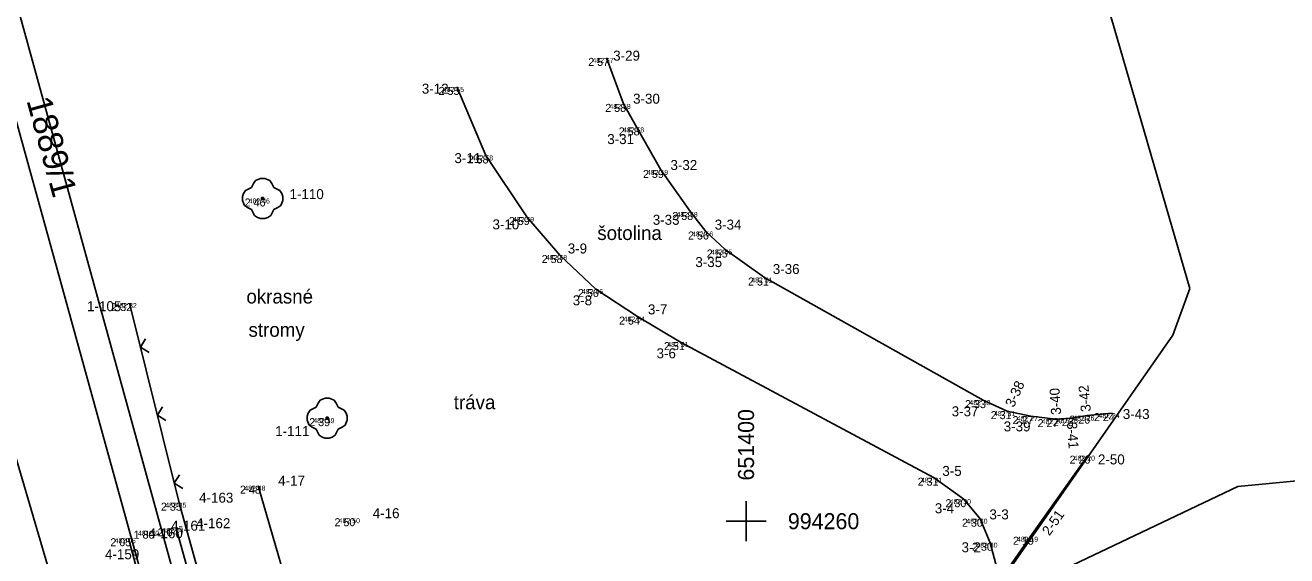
# Model space of a CAD drawing. Extents: x -651478 to -651308, y -994378 to -994071.
# Drawn here: x -651414.41 to -651389.19, y -994260.69 to -994250.09 of the extents above; entities that cross this region are included whole.
import ezdxf

# ---------------------------------------------------------------- set-up
doc = ezdxf.new("R2010")
doc.units = 0
for name, color, linetype in [('13_POPIS_POLOHOPISU', 7, 'Continuous'), ('18_TECKY_BODU', 7, 'Continuous'), ('19_CISLA_BODU', 7, 'Continuous'), ('20_REDUKOVANE_VYSKY_BODU', 7, 'Continuous'), ('21_SOUVISLA_ZELEN', 7, 'Continuous'), ('22_JEDNOTL_STROMY', 7, 'Continuous'), ('23_BREHOVA_CARA', 7, 'Continuous'), ('25_CHODNIKY', 7, 'Continuous'), ('26_PLOTY', 7, 'Continuous'), ('38_VODA-VEDENI', 7, 'Continuous'), ('61_UPLNE_VYSKY_BODU', 7, 'Continuous'), ('_KM', 7, 'Continuous'), ('ROZP', 7, 'Continuous')]:
    doc.layers.add(name, color=color, linetype=linetype)

# ---------------------------------------------------------------- blocks, each defined once
blk = doc.blocks.new('POINT_DISPLAY')
blk.add_line((0, 0), (0, 0))
blk = doc.blocks.new('Z24')
for p, q in [((-0.22, 0.22), (-0.18, 0.3)), ((-0.18, 0.3), (-0.14, 0.36)), ((-0.14, 0.36), (-0.04, 0.4)), ((-0.04, 0.4), (0.04, 0.4)), ((0.04, 0.4), (0.14, 0.36)), ((0.14, 0.36), (0.18, 0.3)), ((0.18, 0.3), (0.22, 0.22)), ((-0.4, 0.04), (-0.38, 0.1)), ((-0.4, -0.04), (-0.4, 0.04)), ((-0.38, 0.1), (-0.34, 0.16)), ((-0.34, 0.16), (-0.22, 0.22)), ((-0.02, -0.02), (-0.02, 0.02)), ((-0.02, 0.02), (0.02, 0.02)), ((0.02, 0.02), (0.02, -0.02)), ((0.22, 0.22), (0.34, 0.16)), ((0.34, 0.16), (0.38, 0.1)), ((0.38, 0.1), (0.4, 0.04)), ((0.4, 0.04), (0.4, -0.04)), ((-0.36, -0.14), (-0.4, -0.04)), ((-0.3, -0.18), (-0.36, -0.14)), ((-0.22, -0.22), (-0.3, -0.18)), ((-0.16, -0.34), (-0.22, -0.22)), ((0.02, -0.02), (-0.02, -0.02)), ((0.22, -0.22), (0.16, -0.34)), ((0.3, -0.18), (0.22, -0.22)), ((0.36, -0.14), (0.3, -0.18)), ((0.4, -0.04), (0.36, -0.14)), ((-0.1, -0.38), (-0.16, -0.34)), ((-0.04, -0.4), (-0.1, -0.38)), ((0.04, -0.4), (-0.04, -0.4)), ((0.1, -0.38), (0.04, -0.4)), ((0.16, -0.34), (0.1, -0.38))]:
    blk.add_line(p, q)
blk = doc.blocks.new('Z212')
for p, q in [((-0.14, 0.14), (0, 0)), ((0, 0), (0.14, 0.14))]:
    blk.add_line(p, q)
blk = doc.blocks.new('Z70')
for p, q in [((0, -0.4), (0, 0.4)), ((-0.4, 0), (0.4, 0))]:
    blk.add_line(p, q)

msp = doc.modelspace()

# ---------------------------------------------------------------- linework, layer by layer
at = {"layer": '21_SOUVISLA_ZELEN'}
msp.add_line((-651409.75, -994259.29), (-651408.32, -994264.21), dxfattribs=at)
at = {"layer": '23_BREHOVA_CARA'}
for p, q in [((-651411.39, -994260.14), (-651409.85, -994265.67)), ((-651410.87, -994265.87), (-651412.34, -994260.34))]:
    msp.add_line(p, q, dxfattribs=at)
at = {"layer": '25_CHODNIKY'}
for p, q in [((-651402.79, -994250.74), (-651402.45, -994251.66)), ((-651405.2, -994252.69), (-651405.78, -994251.32)), ((-651402.45, -994251.66), (-651402.18, -994252.13)), ((-651402.18, -994252.13), (-651401.7, -994252.98)), ((-651404.38, -994253.92), (-651405.2, -994252.69)), ((-651401.7, -994252.98), (-651401.11, -994253.82)), ((-651401.11, -994253.82), (-651400.8, -994254.21)), ((-651403.72, -994254.68), (-651404.38, -994253.92)), ((-651400.8, -994254.21), (-651400.42, -994254.57)), ((-651400.42, -994254.57), (-651399.63, -994255.13)), ((-651403, -994255.36), (-651403.72, -994254.68)), ((-651402.17, -994255.91), (-651403, -994255.36)), ((-651399.63, -994255.13), (-651395.26, -994257.58)), ((-651401.31, -994256.42), (-651402.17, -994255.91)), ((-651396.24, -994259.13), (-651401.31, -994256.42)), ((-651395.26, -994257.58), (-651394.78, -994257.8)), ((-651394.78, -994257.8), (-651394.31, -994257.9)), ((-651393.18, -994257.89), (-651392.68, -994257.84)), ((-651394.31, -994257.9), (-651393.81, -994257.96)), ((-651393.81, -994257.96), (-651393.51, -994257.94)), ((-651393.51, -994257.94), (-651393.18, -994257.89)), ((-651394.32, -994260.31), (-651393.17, -994258.69)), ((-651395.65, -994259.56), (-651396.24, -994259.13)), ((-651395.32, -994259.95), (-651395.65, -994259.56)), ((-651395.12, -994260.43), (-651395.32, -994259.95)), ((-651397.73, -994265.24), (-651394.32, -994260.31)), ((-651394.96, -994261.03), (-651395.12, -994260.43))]:
    msp.add_line(p, q, dxfattribs=at)
at = {"layer": '26_PLOTY'}
for p, q in [((-651411.33, -994259.63), (-651412.32, -994255.64)), ((-651409.69, -994265.51), (-651411.33, -994259.63))]:
    msp.add_line(p, q, dxfattribs=at)
at = {"layer": '38_VODA-VEDENI'}
for p, q in [((-651396.169, -994262.153), (-651390.168, -994259.308)), ((-651390.168, -994259.308), (-651388.919, -994259.187))]:
    msp.add_line(p, q, dxfattribs=at)
at = {"layer": '_KM'}
for p, q in [((-651417.67, -994238.38), (-651407.11, -994276.82)), ((-651418.3, -994238.56), (-651407.69, -994276.96)), ((-651420.36, -994239.17), (-651409.08, -994277.42)), ((-651391.13, -994255.35), (-651394.42, -994244.03)), ((-651391.47, -994256.28), (-651391.13, -994255.35)), ((-651397.73, -994265.24), (-651391.47, -994256.28))]:
    msp.add_line(p, q, dxfattribs=at)

# ---------------------------------------------------------------- block references
at = {"layer": '18_TECKY_BODU'}
for p in [(-651402.79, -994250.74), (-651405.78, -994251.32), (-651402.45, -994251.66), (-651402.18, -994252.13), (-651405.2, -994252.69), (-651401.7, -994252.98), (-651409.66, -994253.55), (-651401.11, -994253.82), (-651404.38, -994253.92), (-651400.8, -994254.21), (-651400.42, -994254.57), (-651403.72, -994254.68), (-651403, -994255.36), (-651399.63, -994255.13), (-651412.32, -994255.64), (-651402.17, -994255.91), (-651401.31, -994256.42), (-651395.26, -994257.58), (-651394.78, -994257.8), (-651392.68, -994257.84), (-651408.37, -994257.94), (-651394.31, -994257.9), (-651393.81, -994257.96), (-651393.51, -994257.94), (-651393.18, -994257.89), (-651393.17, -994258.69), (-651396.24, -994259.13), (-651409.75, -994259.29), (-651411.33, -994259.63), (-651395.65, -994259.56), (-651411.39, -994260.14), (-651407.86, -994259.94), (-651395.32, -994259.95), (-651412.34, -994260.34), (-651411.89, -994260.19), (-651394.32, -994260.31), (-651395.12, -994260.43)]:
    msp.add_blockref('POINT_DISPLAY', p, dxfattribs=at)
at = {"layer": '22_JEDNOTL_STROMY'}
for p in [(-651409.66, -994253.55), (-651408.37, -994257.94)]:
    msp.add_blockref('Z24', p, dxfattribs=at)
at = {"layer": '26_PLOTY', "rotation": -76.10000000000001}
for p in [(-651412.101, -994256.524), (-651411.763, -994257.883), (-651411.426, -994259.242)]:
    msp.add_blockref('Z212', p, dxfattribs=at)
at = {"layer": 'ROZP'}
msp.add_blockref('Z70', (-651400, -994260), dxfattribs=at)

# ---------------------------------------------------------------- texts
at = {"layer": '13_POPIS_POLOHOPISU'}
for s, p in [('šotolina', (-651402.973, -994254.38)), ('okrasné', (-651409.985, -994255.649)), ('stromy', (-651409.943, -994256.314)), ('tráva', (-651405.841, -994257.763))]:
    msp.add_text(s, height=0.28, dxfattribs=at).set_placement(p)
at = {"layer": '19_CISLA_BODU'}
for s, p in [('3-29', (-651402.655, -994250.795)), ('3-12', (-651406.479, -994251.455)), ('3-30', (-651402.257, -994251.656)), ('3-31', (-651402.773, -994252.463)), ('3-11', (-651405.828, -994252.843)), ('3-32', (-651401.51, -994252.981)), ('1-110', (-651409.123, -994253.563)), ('3-10', (-651405.067, -994254.167)), ('3-33', (-651401.864, -994254.076)), ('3-34', (-651400.626, -994254.172)), ('3-9', (-651403.563, -994254.649)), ('3-35', (-651401.013, -994254.921)), ('3-36', (-651399.465, -994255.06)), ('1-105', (-651413.169, -994255.803)), ('3-8', (-651403.463, -994255.685)), ('3-7', (-651401.96, -994255.867)), ('3-6', (-651401.788, -994256.744)), ('3-37', (-651395.89, -994257.903)), ('3-43', (-651392.47, -994257.958)), ('1-111', (-651409.41, -994258.3)), ('3-39', (-651394.85, -994258.205)), ('3-5', (-651396.077, -994259.095)), ('2-50', (-651392.967, -994258.865)), ('4-17', (-651409.35, -994259.29)), ('4-163', (-651410.93, -994259.63)), ('3-4', (-651396.227, -994259.841)), ('4-16', (-651407.46, -994259.94)), ('3-3', (-651395.136, -994259.964)), ('4-160', (-651411.94, -994260.34)), ('4-161', (-651411.49, -994260.19)), ('4-162', (-651410.99, -994260.14)), ('4-159', (-651412.81, -994260.76)), ('3-2', (-651395.693, -994260.621))]:
    msp.add_text(s, height=0.2, dxfattribs=at).set_placement(p)
for s, rotation, p in [('3-38', 65.3764, (-651394.649, -994257.739)), ('3-40', 93.8142, (-651393.702, -994257.866)), ('3-42', 95.7106, (-651393.106, -994257.804)), ('3-41', 273.8142, (-651393.586, -994258.025)), ('2-51', 54.63, (-651393.937, -994260.303))]:
    msp.add_text(s, height=0.2, rotation=rotation, dxfattribs=at).set_placement(p)
at = {"layer": '20_REDUKOVANE_VYSKY_BODU'}
for s, p in [(' 2 57', (-651403.213, -994250.9)), (' 2 55', (-651406.203, -994251.48)), (' 2 58', (-651402.873, -994251.82)), (' 2 58', (-651402.603, -994252.29)), (' 2 58', (-651405.623, -994252.85)), (' 2 59', (-651402.119, -994253.14)), (' 2 46', (-651410.079, -994253.71)), (' 2 58', (-651401.533, -994253.98)), (' 2 59', (-651404.799, -994254.08)), (' 2 56', (-651401.219, -994254.37)), (' 2 55', (-651400.843, -994254.73)), (' 2 58', (-651404.143, -994254.84)), (' 2 56', (-651403.419, -994255.52)), (' 2 51', (-651400.019, -994255.29)), (' 2 32', (-651412.743, -994255.8)), (' 2 54', (-651402.597, -994256.07)), (' 2 51', (-651401.699, -994256.58)), (' 2 33', (-651395.683, -994257.74)), (' 2 31', (-651395.169, -994257.96)), (' 2 24', (-651393.107, -994258)), (' 2 39', (-651408.789, -994258.1)), (' 2 27', (-651394.733, -994258.06)), (' 2 27', (-651394.233, -994258.12)), (' 2 26', (-651393.929, -994258.1)), (' 2 26', (-651393.599, -994258.05)), (' 2 20', (-651393.593, -994258.85)), (' 2 31', (-651396.629, -994259.29)), (' 2 48', (-651410.173, -994259.45)), (' 2 35', (-651411.753, -994259.79)), (' 2 30', (-651396.073, -994259.72)), (' 2 04', (-651411.817, -994260.3)), (' 2 50', (-651408.283, -994260.1)), (' 2 30', (-651395.743, -994260.11)), (' 2 05', (-651412.763, -994260.5)), (' 1 80', (-651412.298, -994260.35)), (' 2 19', (-651394.724, -994260.47)), (' 2 30', (-651395.543, -994260.59))]:
    msp.add_text(s, height=0.16, dxfattribs=at).set_placement(p)
at = {"layer": '61_UPLNE_VYSKY_BODU'}
for s, p in [('482 57 ', (-651403.068, -994250.84)), ('482 55 ', (-651406.058, -994251.42)), ('482 58 ', (-651402.728, -994251.76)), ('482 58 ', (-651402.458, -994252.23)), ('482 58 ', (-651405.478, -994252.79)), ('482 59 ', (-651401.979, -994253.08)), ('482 46 ', (-651409.938, -994253.65)), ('482 58 ', (-651401.388, -994253.92)), ('482 59 ', (-651404.659, -994254.02)), ('482 56 ', (-651401.079, -994254.31)), ('482 55 ', (-651400.698, -994254.67)), ('482 58 ', (-651403.998, -994254.78)), ('482 56 ', (-651403.279, -994255.46)), ('482 51 ', (-651399.894, -994255.23)), ('482 32 ', (-651412.598, -994255.74)), ('482 54 ', (-651402.447, -994256.01)), ('482 51 ', (-651401.574, -994256.52)), ('482 33 ', (-651395.536, -994257.68)), ('482 31 ', (-651395.043, -994257.9)), ('482 24 ', (-651392.958, -994257.94)), ('482 39 ', (-651408.648, -994258.04)), ('482 27 ', (-651394.589, -994258)), ('482 27 ', (-651394.089, -994258.06)), ('482 26 ', (-651393.79, -994258.04)), ('482 26 ', (-651393.46, -994257.99)), ('482 20 ', (-651393.449, -994258.79)), ('482 31 ', (-651396.503, -994259.23)), ('482 48 ', (-651410.027, -994259.39)), ('482 35 ', (-651411.607, -994259.73)), ('482 30 ', (-651395.927, -994259.66)), ('482 04 ', (-651411.667, -994260.24)), ('482 50 ', (-651408.138, -994260.04)), ('482 30 ', (-651395.597, -994260.05)), ('482 05 ', (-651412.618, -994260.44)), ('481 80 ', (-651412.153, -994260.29)), ('482 19 ', (-651394.585, -994260.41)), ('482 30 ', (-651395.397, -994260.53))]:
    msp.add_text(s, height=0.1, dxfattribs=at).set_placement(p)
at = {"layer": '_KM'}
msp.add_text('1889/1', height=0.5, rotation=285.361, dxfattribs=at).set_placement((-651414.384, -994251.59))
at = {"layer": 'ROZP'}
msp.add_text('651400', height=0.32, rotation=90, dxfattribs=at).set_placement((-651399.84, -994259.187))
msp.add_text('994260', height=0.32, dxfattribs=at).set_placement((-651399.164, -994260.16))

doc.saveas('drawing.dxf')
